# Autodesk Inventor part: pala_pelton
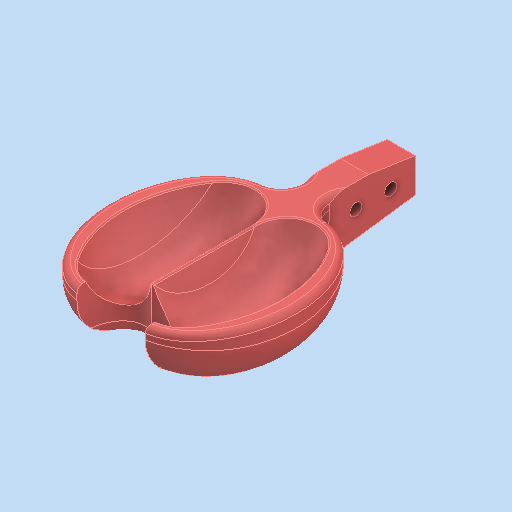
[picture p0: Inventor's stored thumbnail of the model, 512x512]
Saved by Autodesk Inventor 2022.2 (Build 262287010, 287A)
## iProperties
Created: 2024-02
Part Number: pala_pelton
Material: Acciaio inossidabile
Document SubType Name: Modeling
Designer: 18907419
Density: 8 g/cm^3
Appearance: Default
Author: 18907419
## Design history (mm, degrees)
feature "Solido1"
node "Solido2"
